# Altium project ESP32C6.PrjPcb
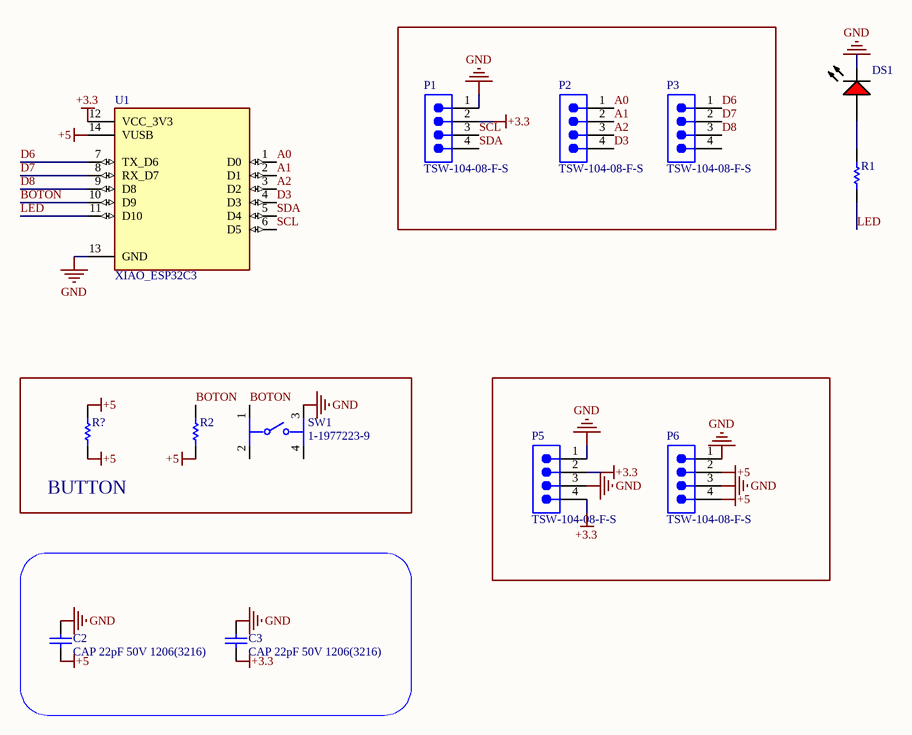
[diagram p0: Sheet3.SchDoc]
1 sheet, 13 parts. Net scope: global (net labels, ports and power ports of the same name join across sheets).
Board file: PCB2.PcbDoc

## Sheet Sheet3.SchDoc
size A4; SheetNumber: 1; SheetTotal: 1

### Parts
C2  CAP 22pF 50V 1206(3216)  [CAPC1206(3216)100_M]
C3  CAP 22pF 50V 1206(3216)  [CAPC1206(3216)100_M]
DS1  SML-LX1206IC-TR  [LUMX-SML-LX1206IC_V]  (value not drawn)
P1  TSW-104-08-F-S  [SMTC-TSW-104-08-X-S]
P2  TSW-104-08-F-S  [SMTC-TSW-104-08-X-S]
P3  TSW-104-08-F-S  [SMTC-TSW-104-08-X-S]
P5  TSW-104-08-F-S  [SMTC-TSW-104-08-X-S]
P6  TSW-104-08-F-S  [SMTC-TSW-104-08-X-S]
R1  (no value)  [RESC3116X65X40NL10T20]
R2  RC1206FR-076R98L  [RESC3116X65X40NL10T20]  (value not drawn)
R?  RC1206FR-076R98L  [RESC3116X65X40NL10T20]  (value not drawn)
SW1  1-1977223-9  [FP-1-1977223-9-MFG]
U1  XIAO_ESP32C3  [MODULE_XIAO_ESP32C3]

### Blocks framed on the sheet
BUTTON: R2 R? SW1

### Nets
+3.3: C3.1 P1.2 P5.2 P5.4 U1.12(VCC_3V3)
+5: C2.1 P6.2 P6.4 R2.1 R?.1 R?.2 U1.14(VUSB)
GND: C2.2 C3.2 DS1.2(K) P1.1 P5.1 P5.3 P6.1 P6.3 SW1.3 U1.13(GND)
A0: P2.1 U1.1(D0)
A1: P2.2 U1.2(D1)
A2: P2.3 U1.3(D2)
BOTON: R2.2 SW1.1 U1.10(D9)
D3: P2.4 U1.4(D3)
D6: P3.1 U1.7(TX_D6)
D7: P3.2 U1.8(RX_D7)
D8: P3.3 U1.9(D8)
LED: R1.1 U1.11(D10)
SCL: P1.3 U1.6(D5)
SDA: P1.4 U1.5(D4)
NetDS1_1: DS1.1(A) R1.2

Not connected (* = marked no-connect by the designer): P3 4; SW1 2 4

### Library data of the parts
C2 C3 = CMP-1037-00980-1: CAP 22pF 50V ±10% 1206 (3216 Metric) Thickness 1mm SMD; Case-Metric: 3216; Case-EIA: 1206; Tolerance: Â±10%
DS1 = CMP-2000-07123-1: LED Red, 65 mW, -40 to 85 degC, 2-Pin SMD, RoHS, Tape and Reel; Manufacturer: Lumex; LED Material: GaAsP; Peak Wavelength: 635nm; Number of LEDs: 1; Viewing Angle: 160; Reverse Voltage: 5(Min)V; Lens Appearance: ColorlessNonDiffused; Intensity: 6mcd; Type: Uni-Color; Pin_Count: 2
P1-P3 P5 P6 = CMP-1024-00355-1: 0.025" SQ Post Header, Through-hole, Vertical, -55 to 125 degC, 2.54 mm Pitch, 4-Pin, Male, RoHS; Manufacturer: Samtec; Pitch: 2.54 mm
R1 = CMP-2003-03854-1: Manufacturer: Yageo; Part Number: RC1206FR-076R98L
R2 R? = CMP-2003-03854-1: Manufacturer: Yageo
SW1 = CMP-03407-000015-1: SWITCH TACTILE SPST-NO 0.05A 24V; Current Rating: 50mA; Operating Force: 2.55N; Throw Configuration: SPST; Actuator Material: Nylon; Actuator Color: Pink; Mechanical Life: 1000000Cycles; Illumination Type: Non-Illuminated; Switch Travel: 0.25mm; Switch Function: Off-Mom; Actuator Type: Standard
U1 = XIAO_ESP32C3: Dev.kit: evaluation; u.FL antenna,prototype board; XIAO; PIN: 2x7; MF: Seeed Studio; MP: XIAO ESP32C3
